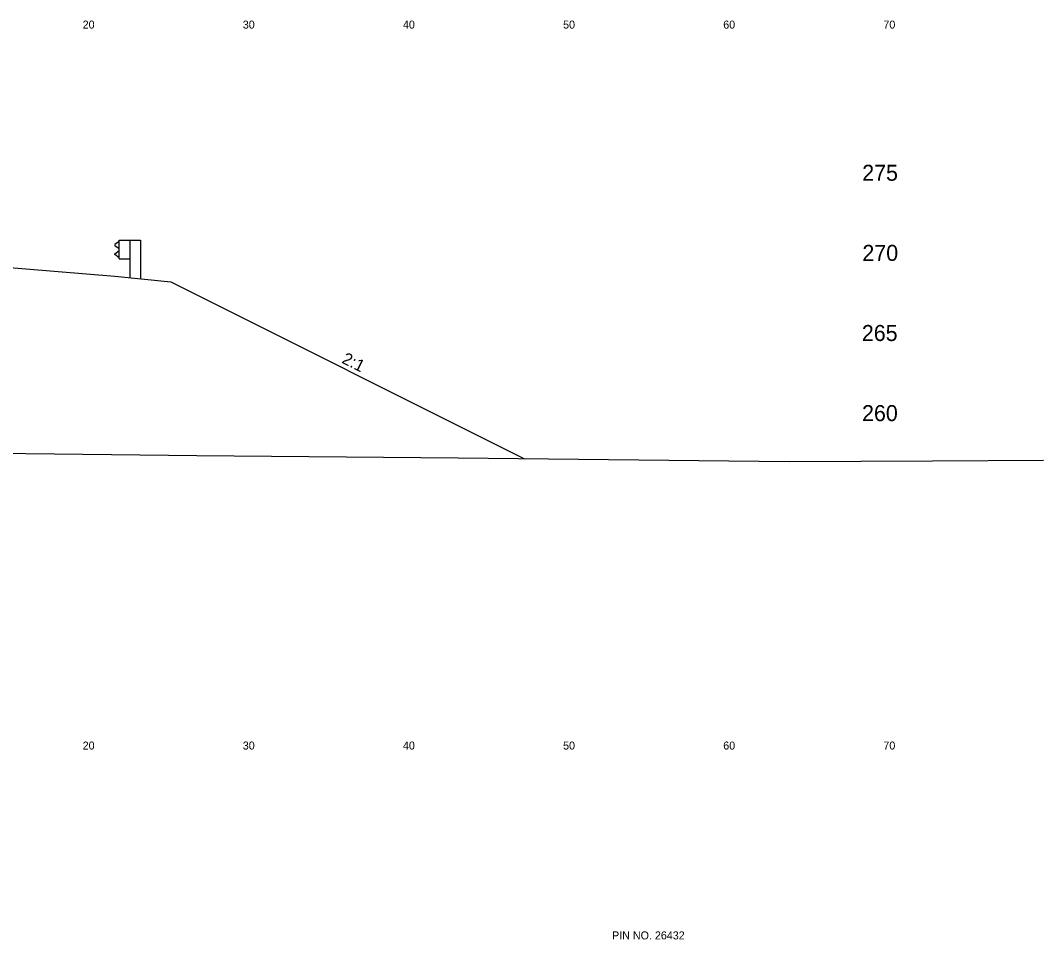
# Model space of a CAD drawing. Extents: x 1000 to 1162, y 999 to 8520.
# Drawn here: x 1096.1 to 1160, y 4897.6 to 4955 of the extents above; entities that cross this region are included whole.
import ezdxf

# ---------------------------------------------------------------- set-up
doc = ezdxf.new("R2010")
doc.units = 0
for name, color, linetype in [('Level 11', 7, 'Continuous'), ('Level 20', 7, 'Continuous'), ('Level 24', 7, 'Continuous'), ('Level 32', 7, 'Continuous'), ('Level 56', 7, 'Continuous'), ('Level 6', 7, 'Continuous'), ('Level 60', 7, 'Continuous'), ('Level 7', 7, 'Continuous')]:
    doc.layers.add(name, color=color, linetype=linetype)

msp = doc.modelspace()

# ---------------------------------------------------------------- linework, layer by layer
at = {"layer": 'Level 24'}
for p, q in [((1102.271, 4941.219), (1102, 4941.019)), ((1102, 4941.019), (1102, 4940.969)), ((1102, 4940.969), (1102.271, 4940.769)), ((1102.271, 4940.125), (1102.271, 4941.292)), ((1102.271, 4941.292), (1102.937, 4941.292)), ((1102.937, 4941.292), (1102.937, 4938.949)), ((1102.937, 4941.292), (1103.603, 4941.292)), ((1103.603, 4941.292), (1103.603, 4938.882)), ((1102, 4940.448), (1102.271, 4940.648)), ((1102, 4940.398), (1102, 4940.448)), ((1102.271, 4940.198), (1102, 4940.398)), ((1102.271, 4940.125), (1102.938, 4940.125))]:
    msp.add_line(p, q, dxfattribs=at)
at = {"layer": 'Level 6'}
for p, q in [((1094, 4939.709), (1102, 4939.042)), ((1102, 4939.042), (1105.5, 4938.692))]:
    msp.add_line(p, q, dxfattribs=at)
at = {"layer": 'Level 60'}
for p, q in [((1088.481, 4928.088), (1107.127, 4927.851)), ((1107.127, 4927.851), (1123.438, 4927.717)), ((1123.438, 4927.717), (1144.123, 4927.482)), ((1144.123, 4927.482), (1153.06, 4927.525)), ((1153.06, 4927.525), (1160, 4927.556))]:
    msp.add_line(p, q, dxfattribs=at)
at = {"layer": 'Level 7'}
msp.add_line((1105.5, 4938.692), (1127.544, 4927.67), dxfattribs=at)

# ---------------------------------------------------------------- texts
at = {"layer": 'Level 11'}
for s, p in [(' 275', (1148.307, 4945)), (' 270', (1148.319, 4940)), (' 265', (1148.284, 4935)), (' 260', (1148.295, 4930))]:
    msp.add_text(s, height=1, dxfattribs=at).set_placement(p)
at = {"layer": 'Level 20'}
msp.add_text('PIN NO. 26432', height=0.5, dxfattribs=at).set_placement((1133.058, 4897.65))
at = {"layer": 'Level 32'}
msp.add_text('2:1', height=0.75, rotation=333.43495, dxfattribs=at).set_placement((1116.127, 4933.658))
at = {"layer": 'Level 56'}
for s, p in [('20', (1100, 4954.5)), ('30', (1110, 4954.5)), ('40', (1120, 4954.5)), ('50', (1130, 4954.5)), ('60', (1140, 4954.5)), ('70', (1150, 4954.5)), ('20', (1100, 4909.5)), ('30', (1110, 4909.5)), ('40', (1120, 4909.5)), ('50', (1130, 4909.5)), ('60', (1140, 4909.5)), ('70', (1150, 4909.5))]:
    msp.add_text(s, height=0.5, dxfattribs=at).set_placement(p)

doc.saveas('drawing.dxf')
